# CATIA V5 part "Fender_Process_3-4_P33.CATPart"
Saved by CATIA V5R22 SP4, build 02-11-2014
Part number: Fender
Bounding box of the stored display mesh (mm): x -800 to 0, y -40 to 122.298, z 0 to 580
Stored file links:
  C:\DATA\Car_ASSY\教育モデル\3_SOL\Fender_Process_3-4_P33.CATPart
  C:\DATA\Car_ASSY\教育モデル\3_SOL\Car_Fender.CATPart
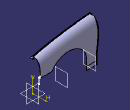
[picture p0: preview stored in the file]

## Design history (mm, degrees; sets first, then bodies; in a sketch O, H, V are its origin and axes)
Set1
  Plane1: type Offset, RefPlane yz-plane, Offset 400, reversed
  Plane2: type Offset, RefPlane Plane1, Offset 400, reversed
Body1 (main body)
Body2
  Sketch1 on yz-plane, origin (0, 0, 0), H (0, 1, 0), V (0, 0, 1)
    point P4 (100, 50)
    point P5 (10, 450)
    spline S1 through (10, 450) (100, 50)
    line L1 (0, 450) -> (10, 450)
    line L2 (0, 0) -> (0, 450)
    line L3 (100, 0) -> (0, 0)
    line L4 (100, 50) -> (100, 0)
    point P6 (100, 50)
    point P7 (10, 450)
    distance P4 L3 = 50
    distance P5 L2 = 10
    distance L4 L2 = 100
    distance L1 H = 450
    coincidence: L2 V, H L3, P4 P6, P7 P5
  Sketch2 on Plane1, origin (-400, 0, 0), H (0, 1, 0), V (0, 0, 1)
    point P4 (100, 50)
    point P5 (10, 530)
    spline S1 through (10, 530) (100, 50)
    line L1 (0, 530) -> (10, 530)
    line L2 (0, 0) -> (0, 530)
    line L3 (100, 0) -> (0, 0)
    line L4 (100, 50) -> (100, 0)
    point P6 (100, 50)
    point P7 (10, 530)
    distance P4 L3 = 50
    distance P5 L2 = 10
    distance L4 L2 = 100
    distance L1 H = 530
    coincidence: L2 V, H L3, P4 P6, P7 P5
  Sketch3 on Plane2, origin (-800, 0, 0), H (0, 1, 0), V (0, 0, 1)
    point P4 (100, 50)
    point P5 (10, 580)
    spline S1 through (10, 580) (100, 50)
    line L1 (0, 580) -> (10, 580)
    line L2 (0, 0) -> (0, 580)
    line L3 (100, 0) -> (0, 0)
    line L4 (100, 50) -> (100, 0)
    point P6 (100, 50)
    point P7 (10, 580)
    distance P4 L3 = 50
    distance P5 L2 = 10
    distance L4 L2 = 100
    distance L1 H = 580
    coincidence: L2 V, H L3, P4 P6, P7 P5
  Loft1: solid, Sections (Sketch1; Sketch2; Sketch3)
  Body3
    Sketch4 on zx-plane, origin (0, 0, 0), H (-1, 0, 0), V (0, 0, 1)
      line L1 (-46.4952, 240) -> (159.0779, 240)
      arc A1 centre (390, 110) radius 265 from (159.0779, 240) to (655, 109.9999) cw
      point P2 (390, 110)
      line L2 (655, 109.9999) -> (655, -30)
      line L3 (-46.4952, 626.6258) -> (850, 626.6258)
      line L4 (850, 626.6258) -> (850, -30)
      line L5 (850, -30) -> (655, -30)
      line L6 (-46.4952, 626.6258) -> (-46.4952, 240)
      radius A1 = 265
      distance P2 H = 110
      distance V P2 = 390
      distance H L1 = 240
      horizontal: L1 H, L3 H, L5 H
      tangency: L2 A1
      vertical: L2 V, L4 V, L6 V
    Pad1: profile Sketch4, direction (0, 1, 0), length 340, mirrored extent
  Intersect1: tool Body3
  Shell1: ExtOffset 0, Face (face of Loft1; face of Loft1; face of Pad1 from Sketch4.A1; face of Pad1 from Sketch4.L1; face of Loft1; face of Loft1), IntOffset 3
  Sketch5 on Plane2, origin (-800, 0, 0), H (0, 1, 0), V (0, 0, 1)
    line L1 (0, 580) -> (0, 545)
    line L2 (-5, 540) -> (-40, 540)
    point P2 (-40, 540)
    reference projected line E1 (10, 580) -> (0, 580)
    reference intersected line E2 (0, 0) -> (0, 580)
    arc A1 centre (-5, 545) radius 5 from (-5, 540) to (0, 545) ccw
    line L3 (-5, 537) -> (-40, 537)
    arc A2 centre (-5, 545) radius 8 from (-5, 537) to (3, 545) ccw
    line L4 (3, 580) -> (3, 545)
    line L5 (-40, 537) -> (-40, 540)
    line L6 (3, 580) -> (0, 580)
    reference projected line E3 (10, 580) -> (0, 580)
    distance E1 L2 = 40
    radius A1 = 5
    distance L1 P2 = 40
    length L5 = 3
    length L6 = 3
    radius A2 = 8
    vertical: L1 V, L4 V, L5 V
    horizontal: L2 H, L6 H, L3 H
    coincidence: L1 E2, L6 E3
    tangency: A1 L2, A1 L1, L4 A2, A2 L3
  Rib1: profile Sketch5, centre curve edge [face of Loft1 | face of Loft1]
  Sketch6 on Plane2, origin (-800, 0, 0), H (0, 1, 0), V (0, 0, 1)
    projected curve E1
    projected line E2 (10, 576.9862) -> (3, 576.9862)
    point P4 (3, 576.9862)
    projected line E3 (3, 576.9862) -> (3, 545)
    projected line E4 (3, 576.9862) -> (3, 399.233)
    point P5 (3, 576.9862)
    projected line E5 (97, 0) -> (97, 50)
    line L1 (97, 0) -> (37, 0)
    line L2 (37, 0) -> (17.9077, 155.4943)
    arc A1 centre (2003, 399.233) radius 2000 from (3, 399.233) to (17.9077, 155.4943) ccw
    angle L1 L2 = 97
    length L1 = 60
    radius A1 = 2000
    horizontal: L1 H
    tangency: A1 E3, A1 L2
    coincidence: P4 P5
  Pad2: profile Sketch6, direction (1, 0, 0), length 10, opposite side length -7
  Sketch7 on yz-plane, origin (0, 0, 0), H (0, 1, 0), V (0, 0, 1)
    projected curve E1
    projected curve E2
    point P1 (103.8705, 240)
    line L1 (100.927, 243) -> (92.1161, 243)
    line L2 (86.1161, 237) -> (86.1161, 160)
    line L3 (86.1161, 160) -> (89.1161, 160)
    line L4 (89.1161, 160) -> (89.1161, 237)
    point P5 (103.8705, 240)
    line L5 (101.1109, 260) -> (104.111, 260)
    point P6 (101.1109, 260)
    point P7 (104.111, 260)
    offset curve E3
    offset curve E4
    line L6 (92.1161, 240) -> (103.8705, 240)
    arc A1 centre (92.1161, 237) radius 3 from (92.1161, 240) to (89.1161, 237) ccw
    arc A2 centre (92.1161, 237) radius 6 from (92.1161, 243) to (86.1161, 237) ccw
    distance L4 L2 = 3
    distance L4 E1 = 15
    distance L1 L6 = 3
    radius A1 = 3
    radius A2 = 6
    distance L6 L3 = 80
    distance L5 L6 = 20
    horizontal: L1 H, L3 H, L5 H, L6 H
    vertical: L2 V, L4 V
    coincidence: P7 E1, E3 P6, P6 L5, P7 L5, P5 P1
    tangency: A1 L6, A1 L4, A2 L1, A2 L2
